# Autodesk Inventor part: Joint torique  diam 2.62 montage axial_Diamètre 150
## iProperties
Shininess: 64.0
Length Units: 11269
Angle Units: 11279
Time Units: 11290
Mass Units: 11283
Length Display Precision: 3
Angle Display Precision: 2
Compacted: True
Part Number: Joint torique  diam 2.62 montage axial_Diamètre 150
Document SubType Name: Modeling
Created: 2006-01
Material: Par défaut
Designer: riri
Density: 0.0
Volumn: 0.0
Area: 0.0
PropertySet Name: Model Information
Control State: 0
Master: False
Checked Out: False
Author: riri
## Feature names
1. Base1
